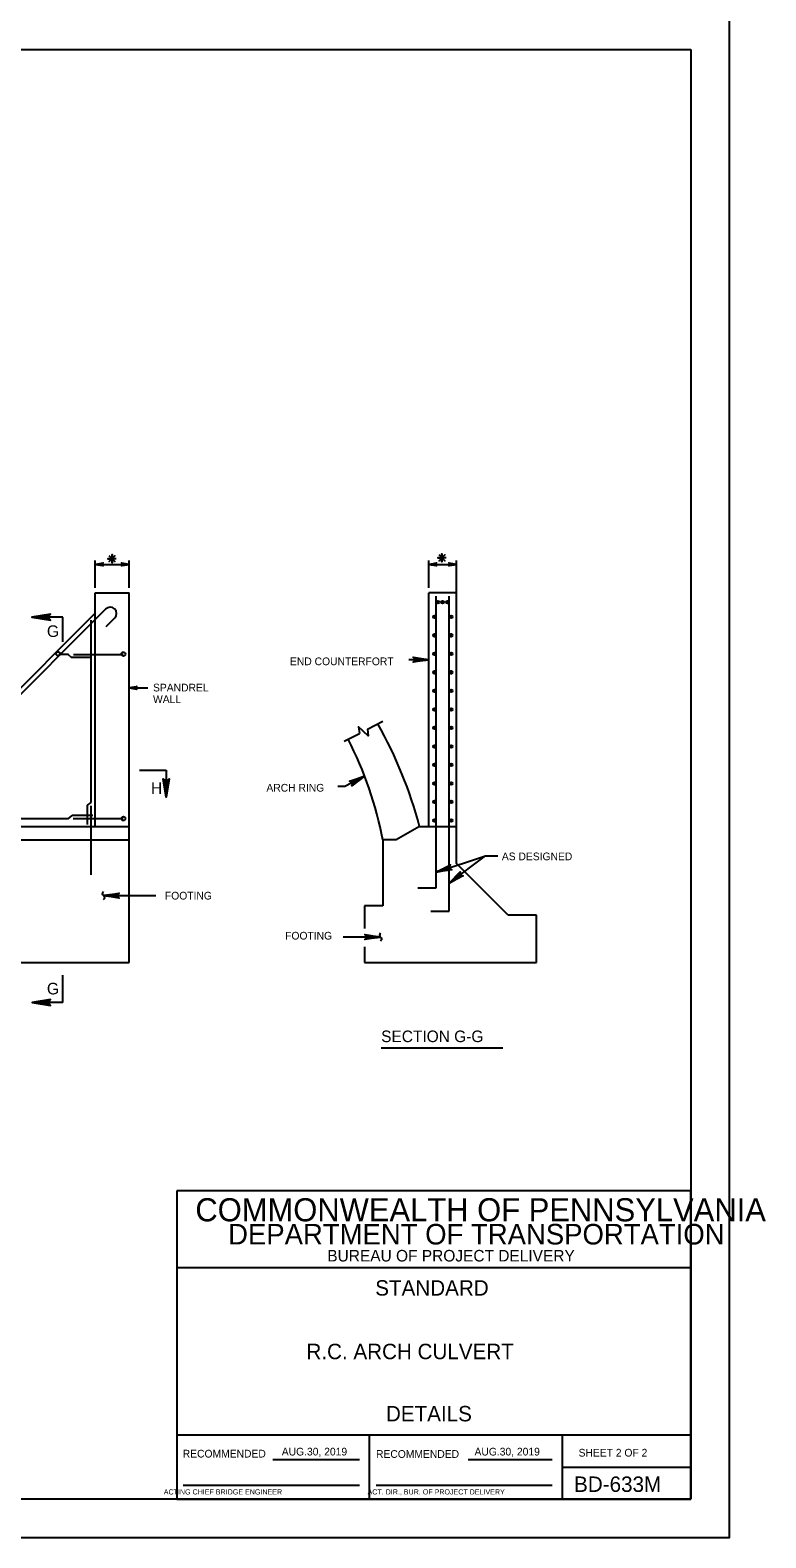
# Model space of a CAD drawing. Extents: x 639028 to 639883, y 298843 to 300031.
# Drawn here: x 639597 to 639883, y 298843 to 299430 of the extents above; entities that cross this region are included whole.
import ezdxf

# ---------------------------------------------------------------- set-up
doc = ezdxf.new("R2010")
doc.units = 0
for name, color, linetype in [('1', 7, 'Continuous'), ('2', 7, 'Continuous'), ('52', 7, 'Continuous'), ('53', 7, 'Continuous'), ('PLT-BNDY', 7, 'Continuous')]:
    doc.layers.add(name, color=color, linetype=linetype)

# ---------------------------------------------------------------- blocks, each defined once
blk = doc.blocks.new('LT')
at = {"layer": '1'}
blk.add_lwpolyline([(0, 0), (-11.2, -2.1), (-10.8, -1.8), (-10.3, -1.5), (-10.1, -1.1), (-9.9, -0.8), (-9.8, -0.4), (-9.8, 0), (-9.8, 0.4), (-9.9, 0.8), (-10.1, 1.1), (-10.3, 1.5), (-10.8, 1.8), (-11.2, 2.1), (0, 0), (-10.8, 1.8), (-10.3, 1.5), (0, 0), (-10.1, 1.1), (-9.9, 0.8), (0, 0), (-9.8, 0.4), (-9.8, 0), (0, 0), (-9.8, -0.4), (-9.9, -0.8), (0, 0), (-10.1, -1.1), (-10.3, -1.5), (0, 0), (-10.8, -1.8)], dxfattribs=at)

msp = doc.modelspace()

# ---------------------------------------------------------------- linework, layer by layer
at = {"layer": '2'}
for p, q in [((639067.74, 299422.08), (639853.74, 299422.08)), ((639853.74, 299422.08), (639853.74, 298858.08)), ((639628.58, 299223.95), (639628.58, 299223.95)), ((639756.96, 299224.31), (639756.96, 299224.31)), ((639622.06, 299210.63), (639635.26, 299210.63)), ((639622.06, 299119.76), (639622.06, 299210.63)), ((639635.26, 299066.93), (639635.26, 299210.63)), ((639762.66, 299210.63), (639751.83, 299210.63)), ((639751.86, 299119.76), (639751.86, 299210.63)), ((639754.74, 299095.98), (639754.74, 299209.43)), ((639759.78, 299086.84), (639759.78, 299209.43)), ((639762.66, 299105.36), (639762.66, 299210.63)), ((639626.2, 299204.43), (639553.07, 299131.3)), ((639622.06, 299202.83), (639582.15, 299162.92)), ((639609.4, 299201.25), (639601.27, 299201.25)), ((639609.4, 299191.68), (639609.4, 299201.25)), ((639620.34, 299200.05), (639620.34, 299129.13)), ((639629.67, 299200.96), (639626.17, 299197.46)), ((639611.62, 299186.71), (639607.81, 299186.71)), ((639611.56, 299186.71), (639612.68, 299185.71)), ((639612.68, 299185.71), (639620.73, 299185.71)), ((639613.53, 299186.71), (639632.89, 299186.71)), ((639727.94, 299157.62), (639733.97, 299160.73)), ((639718.9, 299152.95), (639724.83, 299156.01)), ((639639.22, 299141.66), (639649.59, 299141.66)), ((639649.59, 299141.66), (639649.59, 299131.16)), ((639620.34, 299129.13), (639618.95, 299128.09)), ((639618.95, 299128.09), (639618.95, 299120.51)), ((639620.34, 299127.88), (639620.34, 299101.01)), ((639611.56, 299122.77), (639543.53, 299122.77)), ((639611.56, 299122.77), (639613.05, 299124.1)), ((639621.12, 299124.1), (639613.05, 299124.1)), ((639632.89, 299122.77), (639613.48, 299122.77)), ((639508.96, 299119.76), (639635.26, 299119.76)), ((639748.26, 299119.76), (639739.18, 299114.57)), ((639748.26, 299119.76), (639762.66, 299119.76)), ((639508.96, 299114.57), (639635.26, 299114.57)), ((639733.99, 299114.57), (639733.99, 299088.89)), ((639739.18, 299114.57), (639733.99, 299114.57)), ((639782.72, 299085.3), (639762.66, 299105.36)), ((639747.54, 299095.98), (639754.74, 299095.98)), ((639733.99, 299088.89), (639726.79, 299088.89)), ((639726.79, 299088.89), (639726.79, 299080.06)), ((639752.58, 299086.84), (639759.78, 299086.84)), ((639793.76, 299085.3), (639782.72, 299085.3)), ((639793.76, 299066.93), (639793.76, 299085.3)), ((639726.79, 299072.99), (639726.79, 299066.93)), ((639508.96, 299066.93), (639635.26, 299066.93)), ((639726.79, 299066.93), (639793.76, 299066.93)), ((639609.4, 299051.39), (639609.4, 299061.91)), ((639609.4, 299051.39), (639601.27, 299051.39)), ((639853.74, 298978.08), (639653.74, 298978.08)), ((639653.74, 298978.08), (639653.74, 298858.08)), ((639853.74, 298858.08), (639853.74, 298978.08)), ((639853.74, 298948.08), (639653.74, 298948.08)), ((639853.74, 298883.08), (639653.74, 298883.08)), ((639728.74, 298858.08), (639728.74, 298883.08)), ((639803.74, 298883.08), (639803.74, 298858.08)), ((639691.2, 298873.58), (639724.89, 298873.58)), ((639767.18, 298873.58), (639799.79, 298873.58)), ((639803.74, 298870.58), (639853.74, 298870.58)), ((639656.24, 298863.58), (639724.89, 298863.58)), ((639731.36, 298863.58), (639799.79, 298863.58)), ((639853.74, 298858.08), (639067.74, 298858.08)), ((639653.74, 298858.08), (639853.74, 298858.08))]:
    msp.add_line(p, q, dxfattribs=at)
for points in [[(639630.18, 299223.95), (639626.98, 299223.95), (639628.58, 299223.95), (639628.58, 299222.35), (639628.58, 299225.55), (639628.58, 299223.95), (639629.71, 299225.08), (639627.45, 299222.82), (639628.58, 299223.95), (639629.71, 299222.82), (639627.45, 299225.08)], [(639758.56, 299224.31), (639755.36, 299224.31), (639756.96, 299224.31), (639756.96, 299222.71), (639756.96, 299225.91), (639756.96, 299224.31), (639758.09, 299225.44), (639755.83, 299223.18), (639756.96, 299224.31), (639758.09, 299223.18), (639755.83, 299225.44)], [(639604.27, 299202.12), (639604.02, 299201.62), (639597.4, 299201.25), (639604.27, 299202.12), (639604.65, 299202.37), (639597.4, 299201.25), (639604.02, 299200.87), (639604.27, 299200.37), (639597.4, 299201.25), (639604.65, 299200.12), (639604.27, 299200.37)], [(639727.94, 299157.62), (639728.26, 299155.08), (639724.51, 299158.55), (639724.83, 299156.01)], [(639650.47, 299137.91), (639649.97, 299137.66), (639649.59, 299131.16), (639650.47, 299137.91), (639650.84, 299138.29), (639649.59, 299131.16), (639649.34, 299137.66), (639648.84, 299137.91), (639649.59, 299131.16), (639648.47, 299138.29), (639648.84, 299137.91)], [(639604.27, 299052.14), (639604.02, 299051.64), (639597.52, 299051.39), (639604.27, 299052.14), (639604.65, 299052.52), (639597.52, 299051.39), (639604.02, 299051.02), (639604.27, 299050.52), (639597.52, 299051.39), (639604.65, 299050.14), (639604.27, 299050.52)]]:
    msp.add_lwpolyline(points, dxfattribs=at)
for centre, radius in [((639755.34, 299207.03), 0.533), ((639755.34, 299207.03), 0.4), ((639755.34, 299207.03), 0.267), ((639755.34, 299207.03), 0.133), ((639757.2, 299207.03), 0.533), ((639757.2, 299207.03), 0.4), ((639757.2, 299207.03), 0.267), ((639757.2, 299207.03), 0.133), ((639759.06, 299207.03), 0.533), ((639759.06, 299207.03), 0.4), ((639759.06, 299207.03), 0.267), ((639759.06, 299207.03), 0.133), ((639754.02, 299201.36), 0.533), ((639754.02, 299201.36), 0.4), ((639754.02, 299201.36), 0.267), ((639754.02, 299201.36), 0.133), ((639760.5, 299201.36), 0.533), ((639760.5, 299201.36), 0.4), ((639760.5, 299201.36), 0.267), ((639760.5, 299201.36), 0.133), ((639754.02, 299194.16), 0.533), ((639754.02, 299194.16), 0.4), ((639754.02, 299194.16), 0.267), ((639754.02, 299194.16), 0.133), ((639760.5, 299194.16), 0.533), ((639760.5, 299194.16), 0.4), ((639760.5, 299194.16), 0.267), ((639760.5, 299194.16), 0.133), ((639754.02, 299186.96), 0.533), ((639754.02, 299186.96), 0.4), ((639754.02, 299186.96), 0.267), ((639754.02, 299186.96), 0.133), ((639760.5, 299186.96), 0.533), ((639760.5, 299186.96), 0.4), ((639760.5, 299186.96), 0.267), ((639760.5, 299186.96), 0.133), ((639754.02, 299179.76), 0.533), ((639754.02, 299179.76), 0.4), ((639754.02, 299179.76), 0.267), ((639754.02, 299179.76), 0.133), ((639760.5, 299179.76), 0.533), ((639760.5, 299179.76), 0.4), ((639760.5, 299179.76), 0.267), ((639760.5, 299179.76), 0.133), ((639754.02, 299172.56), 0.533), ((639754.02, 299172.56), 0.4), ((639754.02, 299172.56), 0.267), ((639754.02, 299172.56), 0.133), ((639760.5, 299172.56), 0.533), ((639760.5, 299172.56), 0.4), ((639760.5, 299172.56), 0.267), ((639760.5, 299172.56), 0.133), ((639754.02, 299165.36), 0.533), ((639754.02, 299165.36), 0.4), ((639754.02, 299165.36), 0.267), ((639754.02, 299165.36), 0.133), ((639760.5, 299165.36), 0.533), ((639760.5, 299165.36), 0.4), ((639760.5, 299165.36), 0.267), ((639760.5, 299165.36), 0.133), ((639754.02, 299158.16), 0.533), ((639754.02, 299158.16), 0.4), ((639754.02, 299158.16), 0.267), ((639754.02, 299158.16), 0.133), ((639760.5, 299158.16), 0.533), ((639760.5, 299158.16), 0.4), ((639760.5, 299158.16), 0.267), ((639760.5, 299158.16), 0.133), ((639754.02, 299150.96), 0.533), ((639754.02, 299150.96), 0.4), ((639754.02, 299150.96), 0.267), ((639754.02, 299150.96), 0.133), ((639760.5, 299150.96), 0.533), ((639760.5, 299150.96), 0.4), ((639760.5, 299150.96), 0.267), ((639760.5, 299150.96), 0.133), ((639754.02, 299143.76), 0.533), ((639754.02, 299143.76), 0.4), ((639754.02, 299143.76), 0.267), ((639754.02, 299143.76), 0.133), ((639760.5, 299143.76), 0.533), ((639760.5, 299143.76), 0.4), ((639760.5, 299143.76), 0.267), ((639760.5, 299143.76), 0.133), ((639754.02, 299136.56), 0.533), ((639754.02, 299136.56), 0.4), ((639754.02, 299136.56), 0.267), ((639754.02, 299136.56), 0.133), ((639760.5, 299136.56), 0.533), ((639760.5, 299136.56), 0.4), ((639760.5, 299136.56), 0.267), ((639760.5, 299136.56), 0.133), ((639754.02, 299129.36), 0.533), ((639754.02, 299129.36), 0.4), ((639754.02, 299129.36), 0.267), ((639754.02, 299129.36), 0.133), ((639760.5, 299129.36), 0.533), ((639760.5, 299129.36), 0.4), ((639760.5, 299129.36), 0.267), ((639760.5, 299129.36), 0.133), ((639754.02, 299122.16), 0.533), ((639754.02, 299122.16), 0.4), ((639754.02, 299122.16), 0.267), ((639754.02, 299122.16), 0.133), ((639760.5, 299122.16), 0.533), ((639760.5, 299122.16), 0.4), ((639760.5, 299122.16), 0.267), ((639760.5, 299122.16), 0.133)]:
    msp.add_circle(centre, radius, dxfattribs=at)
for centre, radius, start, end in [((639627.88, 299202.64), 2.45, 316.82004, 136.82004), ((639583.1, 299075.75), 170.93, 14.9198, 29.418), ((639590.49, 299086.72), 146.18, 10.98325, 27.28581)]:
    msp.add_arc(centre, radius, start, end, dxfattribs=at)
at = {"layer": '52'}
for p, q in [((639622.06, 299212.7), (639622.06, 299223.25)), ((639622.06, 299221.75), (639635.26, 299221.75)), ((639635.26, 299212.7), (639635.26, 299223.25)), ((639751.86, 299212.7), (639751.86, 299223.25)), ((639751.86, 299221.75), (639762.66, 299221.75)), ((639762.66, 299210.63), (639762.66, 299223.25))]:
    msp.add_line(p, q, dxfattribs=at)
for points in [[(639746.07, 299185.4), (639746.28, 299184.98), (639751.86, 299184.67), (639746.07, 299185.4), (639745.77, 299185.65), (639751.86, 299184.67), (639746.29, 299184.39), (639746.08, 299183.98), (639751.86, 299184.67), (639745.77, 299183.7), (639746.08, 299183.98)], [(639751.86, 299184.67), (639744.04, 299184.67)], [(639635.26, 299173.74), (639638.24, 299174.3), (639638.12, 299174.22), (639638.01, 299174.14), (639637.95, 299174.04), (639637.89, 299173.94), (639637.87, 299173.84), (639637.86, 299173.74), (639637.87, 299173.64), (639637.89, 299173.54), (639637.95, 299173.44), (639638.01, 299173.34), (639638.12, 299173.26), (639638.24, 299173.18), (639635.26, 299173.74), (639638.12, 299173.26), (639638.01, 299173.34), (639635.26, 299173.74), (639637.95, 299173.44), (639637.89, 299173.54), (639635.26, 299173.74), (639637.87, 299173.64), (639637.86, 299173.74), (639635.26, 299173.74), (639637.87, 299173.84), (639637.89, 299173.94), (639635.26, 299173.74), (639637.95, 299174.04), (639638.01, 299174.14), (639635.26, 299173.74), (639638.12, 299174.22)], [(639635.26, 299173.74), (639642.5, 299173.74)], [(639726.85, 299139.38), (639719.21, 299135.35), (639716.37, 299135.35)], [(639721.38, 299137.32), (639721.77, 299137.05), (639726.85, 299139.38), (639721.38, 299137.32), (639721, 299137.4), (639726.85, 299139.38), (639722.05, 299136.53), (639722.06, 299136.07), (639726.85, 299139.38), (639721.91, 299135.68), (639722.06, 299136.07)], [(639754.74, 299101.99), (639773.83, 299108.38), (639778.73, 299108.38)], [(639760.48, 299103.14), (639760.14, 299103.47), (639754.74, 299101.99), (639760.48, 299103.14), (639760.84, 299103), (639754.74, 299101.99), (639759.95, 299104.03), (639760.01, 299104.48), (639754.74, 299101.99), (639760.22, 299104.85), (639760.01, 299104.48)], [(639759.78, 299097.73), (639773.83, 299108.38)], [(639764.85, 299100.66), (639764.42, 299100.86), (639759.78, 299097.73), (639764.85, 299100.66), (639765.24, 299100.64), (639759.78, 299097.73), (639764.06, 299101.33), (639763.98, 299101.78), (639759.78, 299097.73), (639764.06, 299102.19), (639763.98, 299101.78)], [(639631.09, 299092.18), (639630.87, 299092.6), (639625.29, 299092.91), (639631.09, 299092.18), (639631.39, 299091.93), (639625.29, 299092.91), (639630.87, 299093.19), (639631.07, 299093.6), (639625.29, 299092.91), (639631.39, 299093.88), (639631.07, 299093.6)], [(639625.29, 299092.91), (639645.66, 299092.91)], [(639733.04, 299076.8), (639718.5, 299076.8)], [(639727.24, 299077.53), (639727.46, 299077.11), (639733.04, 299076.8), (639727.24, 299077.53), (639726.94, 299077.78), (639733.04, 299076.8), (639727.46, 299076.52), (639727.26, 299076.11), (639733.04, 299076.8), (639726.94, 299075.83), (639727.26, 299076.11)]]:
    msp.add_lwpolyline(points, dxfattribs=at)
for centre in [(639607.58, 299186.98), (639633.01, 299186.86), (639633.01, 299122.9)]:
    msp.add_circle(centre, 0.771, dxfattribs=at)
for points in [[(639625.26, 299091.35), (639625.72, 299092.22), (639624.86, 299093.61), (639625.27, 299094.47)], [(639733.07, 299078.36), (639732.61, 299077.49), (639733.48, 299076.1), (639733.06, 299075.24)]]:
    msp.add_spline(points, degree=3, dxfattribs=at)
at = {"layer": '53'}
msp.add_line((639733.31, 299033.67), (639780.68, 299033.67), dxfattribs=at)
at = {"layer": 'PLT-BNDY'}
msp.add_lwpolyline([(639027.74, 299437.08), (639868.74, 299437.08), (639868.74, 298843.08), (639027.74, 298843.08)], close=True, dxfattribs=at)

# ---------------------------------------------------------------- block references
at = {"layer": '52', "xscale": 0.2682193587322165, "yscale": 0.26822435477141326, "rotation": 180}
for p in [(639622.06, 299221.75), (639751.86, 299221.75)]:
    msp.add_blockref('LT', p, dxfattribs=at)
at = {"layer": '52', "xscale": 0.2682193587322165, "yscale": 0.26822435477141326}
for p in [(639635.26, 299221.75), (639762.66, 299221.75)]:
    msp.add_blockref('LT', p, dxfattribs=at)

# ---------------------------------------------------------------- texts
at = {"layer": '2'}
for s, height, p in [('G', 4.52, (639603.24, 299193.52)), ('END COUNTERFORT', 3, (639697.81, 299182.54)), ('SPANDREL', 3, (639644.52, 299172.33)), ('WALL', 3, (639644.52, 299167.83)), ('H', 4.5, (639643.74, 299132.5)), ('ARCH RING', 3, (639688.64, 299133.37)), ('AS DESIGNED', 3, (639780.25, 299106.67)), ('FOOTING', 3, (639649.15, 299091.39)), ('FOOTING', 3, (639695.93, 299075.81)), ('G', 4.52, (639603.24, 299054.48)), ('COMMONWEALTH OF PENNSYLVANIA', 9, (639660.99, 298966.2)), ('DEPARTMENT OF TRANSPORTATION', 8.0002, (639673.74, 298957.2)), ('BUREAU OF PROJECT DELIVERY', 4.5, (639712.33, 298950.58)), ('STANDARD', 6, (639730.99, 298937.31)), ('R.C. ARCH CULVERT', 6, (639704.22, 298912.58)), ('DETAILS', 6, (639735.15, 298888.39)), ('AUG.30, 2019', 3, (639694.62, 298875.12)), ('AUG.30, 2019', 3, (639769.62, 298875.12)), ('SHEET 2 OF 2', 3, (639810.11, 298874.7)), ('BD-633M', 6, (639808.36, 298860.95)), ('       ACTING CHIEF BRIDGE ENGINEER', 2.0002, (639643.33, 298859.95)), ('   ACT. DIR., BUR. OF PROJECT DELIVERY', 2.0002, (639725.69, 298859.96))]:
    msp.add_text(s, height=height, dxfattribs=at).set_placement(p)
for p in [(639656.08, 298874.33), (639731.29, 298874.2)]:
    msp.add_text('RECOMMENDED', height=3, rotation=360, dxfattribs=at).set_placement(p)
at = {"layer": '53'}
msp.add_text('SECTION G-G', height=4.5, dxfattribs=at).set_placement((639733.29, 299035.92))

doc.saveas('drawing.dxf')
